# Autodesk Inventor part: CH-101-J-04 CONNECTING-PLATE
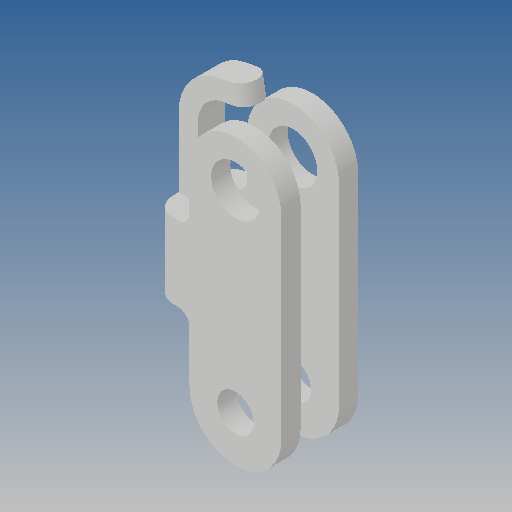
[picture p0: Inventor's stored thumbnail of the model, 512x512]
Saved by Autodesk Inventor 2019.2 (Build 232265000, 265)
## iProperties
Created: 2012-09
Part Number: CH-101-J-04 CONNECTING-PLATE
Material: Ogólny
Document SubType Name: Modeling
Designer: CADENGINEERING4
Density: 1 g/cm^3
Appearance: Domyślna
Author: CADENGINEERING4
Revision Number: ÈÎºÎ
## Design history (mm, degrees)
feature "Ô²½Ç3"
node "Bryła1"
